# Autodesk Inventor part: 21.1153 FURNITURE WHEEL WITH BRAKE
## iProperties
Created: 2007-04
Part Number: 21.1153 FURNITURE WHEEL WITH BRAKE
Document SubType Name: Modeling
Designer: Andy Moles
Material: ABS Plastic
Mass: 76.4383 g
Surface Area: 208.495 cm^2
Volume: 72.1116 cm^3
Density: 1.06 g/cm^3
Author: Andy Moles
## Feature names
1. Base1
